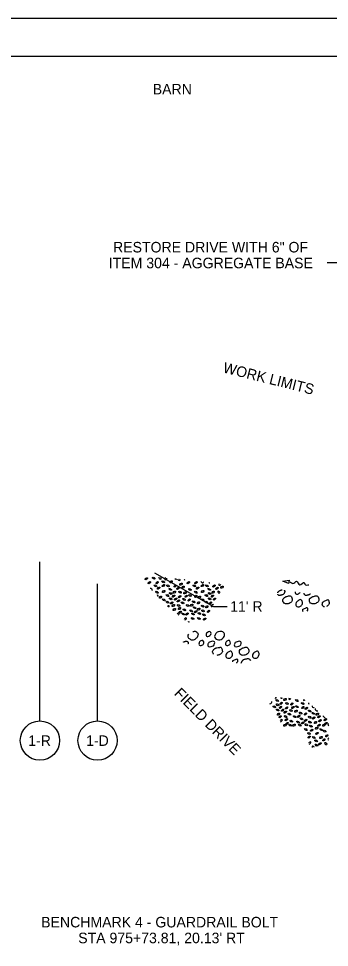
# Model space of a CAD drawing. Extents: x 1785 to 2465, y -264 to 295.
# Drawn here: x 2056 to 2138.7, y -70.6 to 176.2 of the extents above; entities that cross this region are included whole.
import ezdxf

# ---------------------------------------------------------------- set-up
doc = ezdxf.new("R2010")
doc.units = 0
for name, color, linetype in [('DR_P_Cells', 7, 'Continuous'), ('DR_P_Culvert', 7, 'Continuous'), ('DR_X_Erosion_Control', 7, 'Continuous'), ('PV_P_EOP', 7, 'Continuous'), ('PV_P_Shoulder', 7, 'Continuous'), ('RW_X_CL_100_Stations', 7, 'Continuous'), ('SV_X_Shot_Marker', 7, 'Continuous'), ('TX_P_1', 7, 'Continuous')]:
    doc.layers.add(name, color=color, linetype=linetype)

msp = doc.modelspace()

# ---------------------------------------------------------------- linework, layer by layer
at = {"layer": 'DR_P_Culvert'}
for p, q in [((2061.65, -10.42), (2061.65, 31.89)), ((2076.98, -10.42), (2076.98, 26.05))]:
    msp.add_line(p, q, dxfattribs=at)
at = {"layer": 'DR_X_Erosion_Control'}
for centre, major_axis in [((2089.96, 27.38), (0.296, 0.243)), ((2091.92, 27.55), (0.33, -0.195)), ((2090.77, 26.33), (0.296, 0.243)), ((2092.39, 25.49), (0.33, -0.195)), ((2092.84, 26.33), (0.296, 0.243)), ((2093.26, 24.89), (0.296, 0.243)), ((2094.45, 26.54), (0.33, -0.195)), ((2094.48, 25.56), (0.296, 0.243)), ((2095.72, 25.48), (0.33, -0.195)), ((2096.33, 24.56), (0.33, -0.195)), ((2096.57, 26.55), (0.296, 0.243)), ((2097.62, 25.45), (0.296, 0.243)), ((2098.38, 24.82), (0.296, 0.243)), ((2099.2, 25.92), (0.296, 0.243)), ((2099.74, 25.15), (0.296, 0.243)), ((2101.12, 26.33), (0.296, 0.243)), ((2101.55, 24.53), (0.33, -0.195)), ((2102.74, 25.49), (0.33, -0.195)), ((2103.19, 26.33), (0.296, 0.243)), ((2103.61, 24.89), (0.296, 0.243)), ((2104.83, 25.56), (0.296, 0.243)), ((2106.07, 25.48), (0.33, -0.195)), ((2106.68, 24.56), (0.33, -0.195)), ((2107.97, 25.45), (0.296, 0.243)), ((2108.73, 24.82), (0.296, 0.243)), ((2110.09, 25.15), (0.296, 0.243)), ((2092.77, 23.78), (0.33, -0.195)), ((2093.72, 22.49), (0.296, 0.243)), ((2094.59, 23.99), (0.296, 0.243)), ((2095.58, 22.89), (0.33, -0.195)), ((2096.44, 23.44), (0.33, -0.195)), ((2096.44, 22.04), (0.33, -0.195)), ((2097.21, 22.76), (0.296, 0.243)), ((2097.38, 23.8), (0.296, 0.243)), ((2097.74, 21.97), (0.296, 0.243)), ((2098.81, 22.6), (0.296, 0.243)), ((2098.93, 23.78), (0.33, -0.195)), ((2100.22, 23.64), (0.296, 0.243)), ((2100.54, 22.72), (0.296, 0.243)), ((2101.58, 22.92), (0.33, -0.195)), ((2103.12, 23.78), (0.33, -0.195)), ((2103.13, 22.69), (0.296, 0.243)), ((2104.07, 22.49), (0.296, 0.243)), ((2104.94, 23.99), (0.296, 0.243)), ((2105.93, 22.89), (0.33, -0.195)), ((2106.79, 23.44), (0.33, -0.195)), ((2106.79, 22.04), (0.33, -0.195)), ((2107.56, 22.76), (0.296, 0.243)), ((2107.73, 23.8), (0.296, 0.243)), ((2108.09, 21.97), (0.296, 0.243)), ((2094.61, 21.78), (0.33, -0.195)), ((2095.58, 21.16), (0.33, -0.195)), ((2096.68, 20.94), (0.296, 0.243)), ((2097.12, 20.26), (0.296, 0.243)), ((2098.47, 21.48), (0.296, 0.243)), ((2098.56, 20.28), (0.33, -0.195)), ((2098.78, 19.48), (0.296, 0.243)), ((2099.59, 20.96), (0.33, -0.195)), ((2100, 21.89), (0.33, -0.195)), ((2100.96, 20.27), (0.33, -0.195)), ((2101.34, 21.72), (0.296, 0.243)), ((2102.04, 20.36), (0.296, 0.243)), ((2102.57, 21.22), (0.33, -0.195)), ((2102.8, 19.68), (0.33, -0.195)), ((2103.84, 20.97), (0.296, 0.243)), ((2104.96, 21.78), (0.33, -0.195)), ((2104.96, 20.11), (0.33, -0.195)), ((2105.93, 21.16), (0.33, -0.195)), ((2106.04, 19.92), (0.296, 0.243)), ((2107.03, 20.94), (0.296, 0.243)), ((2097.39, 19.21), (0.296, 0.243)), ((2098.97, 18.49), (0.296, 0.243)), ((2099.78, 18), (0.33, -0.195)), ((2100.08, 19.09), (0.33, -0.195)), ((2100.8, 18), (0.296, 0.243)), ((2101.89, 18.84), (0.33, -0.195)), ((2102.36, 18), (0.33, -0.195)), ((2103.08, 18.61), (0.296, 0.243)), ((2103.88, 19.3), (0.296, 0.243)), ((2104.08, 18.12), (0.33, -0.195)), ((2105.04, 18.84), (0.33, -0.195)), ((2105.28, 17.77), (0.33, -0.195)), ((2106.5, 18.71), (0.296, 0.243)), ((2102.27, 16.83), (0.33, -0.195)), ((2103.94, 16.83), (0.33, -0.195)), ((2105.48, 16.66), (0.296, 0.243)), ((2124.77, -4.99), (0.33, -0.195)), ((2126.82, -4.73), (0.296, 0.243)), ((2130, -5.01), (0.33, -0.195)), ((2124.02, -6.65), (0.33, -0.195)), ((2124.89, -6.1), (0.33, -0.195)), ((2124.89, -7.51), (0.33, -0.195)), ((2125.65, -6.79), (0.296, 0.243)), ((2125.83, -5.74), (0.296, 0.243)), ((2126.18, -7.57), (0.296, 0.243)), ((2127.26, -6.95), (0.296, 0.243)), ((2127.37, -5.76), (0.33, -0.195)), ((2128.44, -7.65), (0.33, -0.195)), ((2128.66, -5.91), (0.296, 0.243)), ((2128.99, -6.82), (0.296, 0.243)), ((2130.03, -6.62), (0.33, -0.195)), ((2131.57, -5.77), (0.33, -0.195)), ((2131.58, -6.86), (0.296, 0.243)), ((2132.52, -7.06), (0.296, 0.243)), ((2125.12, -8.61), (0.296, 0.243)), ((2125.56, -9.29), (0.296, 0.243)), ((2126.92, -8.06), (0.296, 0.243)), ((2127, -9.26), (0.33, -0.195)), ((2127.22, -10.07), (0.296, 0.243)), ((2128.03, -8.59), (0.33, -0.195)), ((2129.41, -9.27), (0.33, -0.195)), ((2129.79, -7.82), (0.296, 0.243)), ((2130.48, -9.18), (0.296, 0.243)), ((2131.01, -8.32), (0.33, -0.195)), ((2131.24, -9.86), (0.33, -0.195)), ((2132.29, -8.57), (0.296, 0.243)), ((2133.41, -7.77), (0.33, -0.195)), ((2133.41, -9.44), (0.33, -0.195)), ((2134.37, -8.39), (0.33, -0.195)), ((2134.49, -9.62), (0.296, 0.243)), ((2135.47, -8.61), (0.296, 0.243)), ((2135.91, -9.29), (0.296, 0.243)), ((2137.57, -10.07), (0.296, 0.243)), ((2126.82, -11.55), (0.296, 0.243)), ((2127.42, -11.06), (0.296, 0.243)), ((2128.23, -11.54), (0.33, -0.195)), ((2128.52, -10.45), (0.33, -0.195)), ((2129.25, -11.54), (0.296, 0.243)), ((2130.34, -10.71), (0.33, -0.195)), ((2130.8, -11.54), (0.33, -0.195)), ((2131.53, -10.94), (0.296, 0.243)), ((2132.33, -10.25), (0.296, 0.243)), ((2132.53, -11.42), (0.33, -0.195)), ((2133.48, -10.71), (0.33, -0.195)), ((2133.73, -11.78), (0.33, -0.195)), ((2134.95, -10.84), (0.296, 0.243)), ((2135.28, -12.32), (0.296, 0.243)), ((2135.92, -11.56), (0.296, 0.243)), ((2136.18, -10.33), (0.296, 0.243)), ((2137.17, -11.55), (0.296, 0.243)), ((2137.76, -11.06), (0.296, 0.243)), ((2132.39, -12.72), (0.33, -0.195)), ((2133.24, -13.73), (0.33, -0.195)), ((2133.28, -14.7), (0.296, 0.243)), ((2133.93, -12.89), (0.296, 0.243)), ((2134.52, -14.79), (0.33, -0.195)), ((2135.36, -13.72), (0.296, 0.243)), ((2136.41, -14.82), (0.296, 0.243)), ((2136.48, -12.73), (0.33, -0.195)), ((2137.4, -13.11), (0.33, -0.195)), ((2137.99, -14.35), (0.296, 0.243)), ((2135.12, -15.71), (0.33, -0.195)), ((2135.24, -16.82), (0.33, -0.195)), ((2136.18, -16.47), (0.296, 0.243)), ((2137.17, -15.45), (0.296, 0.243))]:
    msp.add_ellipse(centre, major_axis=major_axis, ratio=0.503326, dxfattribs=at)
for centre, major_axis, start_param, end_param in [((2093.59, 27.55), (0.33, -0.195), 3.081648, 6.283185), ((2093.59, 27.55), (0.33, -0.195), 0, 1.583283), ((2095.13, 27.38), (0.296, 0.243), 1.262331, 5.971541), ((2097.69, 27.54), (0.33, -0.195), 4.661673, 6.283185), ((2097.69, 27.54), (0.33, -0.195), 0, 0.003258), ((2098.61, 27.16), (0.33, -0.195), 3.317728, 6.283185), ((2098.61, 27.16), (0.33, -0.195), 0, 1.347202), ((2100.31, 27.38), (0.296, 0.243), 2.934728, 4.235957), ((2091.2, 24.53), (0.33, -0.195), 0, 2.55882), ((2104.8, 26.54), (0.33, -0.195), 3.736707, 6.283185), ((2104.8, 26.54), (0.33, -0.195), 0, 0.823435), ((2106.92, 26.55), (0.296, 0.243), 2.964771, 4.205915), ((2109.55, 25.92), (0.296, 0.243), 1.874215, 5.29647), ((2091.2, 24.53), (0.33, -0.195), 5.834784, 6.283185), ((2092.78, 22.69), (0.296, 0.243), 0, 1.242704), ((2092.78, 22.69), (0.296, 0.243), 5.112248, 6.283185), ((2109.28, 23.78), (0.33, -0.195), 0.760733, 5.482792), ((2095.69, 19.92), (0.296, 0.243), 0, 1.771206), ((2095.69, 19.92), (0.296, 0.243), 4.746136, 6.283185), ((2107.47, 20.26), (0.296, 0.243), 0, 4.95729), ((2107.47, 20.26), (0.296, 0.243), 5.940076, 6.283185), ((2098.38, 18), (0.296, 0.243), 0, 2.058987), ((2098.38, 18), (0.296, 0.243), 4.458354, 6.283185), ((2100.31, 16.66), (0.296, 0.243), 0, 2.389821), ((2100.31, 16.66), (0.296, 0.243), 4.127521, 6.283185), ((2101.12, 15.61), (0.296, 0.243), 0, 1.432331), ((2101.12, 15.61), (0.296, 0.243), 6.04233, 6.283185), ((2124.17, -4.07), (0.33, -0.195), 5.014572, 6.283185), ((2124.17, -4.07), (0.33, -0.195), 0, 0.813102), ((2126.06, -4.1), (0.296, 0.243), 2.496073, 4.729225), ((2128.18, -4.4), (0.296, 0.243), 2.124737, 5.100561), ((2132.06, -4.66), (0.296, 0.243), 2.449695, 4.775603), ((2123.04, -5.55), (0.296, 0.243), 3.698029, 6.283185), ((2123.04, -5.55), (0.296, 0.243), 0, 0.128607), ((2133.39, -5.55), (0.296, 0.243), 2.151782, 4.285805), ((2134.37, -6.65), (0.33, -0.195), 2.866345, 5.804923), ((2135.24, -7.51), (0.33, -0.195), 2.57753, 6.093738), ((2137.35, -9.26), (0.33, -0.195), 3.0967, 5.574568), ((2125.83, -10.33), (0.296, 0.243), 0, 2.3621), ((2125.83, -10.33), (0.296, 0.243), 3.766158, 6.283185), ((2138.58, -11.54), (0.33, -0.195), 2.00268, 4.858682), ((2133.39, -16.28), (0.296, 0.243), 0, 2.067896), ((2133.39, -16.28), (0.296, 0.243), 3.928937, 6.283185), ((2134.37, -17.38), (0.33, -0.195), 0.77197, 4.49771), ((2137.72, -16.49), (0.33, -0.195), 0, 5.472138), ((2137.72, -16.49), (0.33, -0.195), 6.080726, 6.283185), ((2138.53, -15.12), (0.296, 0.243), 1.180667, 4.317924)]:
    msp.add_ellipse(centre, major_axis=major_axis, ratio=0.503326, start_param=start_param, end_param=end_param, dxfattribs=at)
at = {"layer": 'PV_P_EOP'}
for p, q in [((2126.3, 26.77), (2127.94, 26.97)), ((2127.82, 26.12), (2126.3, 26.77)), ((2127.94, 26.97), (2127.82, 26.12))]:
    msp.add_line(p, q, dxfattribs=at)
msp.add_spline([(2127.88, 26.54), (2127.94, 26.53), (2128.58, 26.29), (2128.97, 26.09), (2129.91, 26.7), (2130.76, 25.74), (2131.98, 26.41), (2132.14, 25.93), (2133.23, 25.79)], degree=3, dxfattribs=at)
at = {"layer": 'PV_P_Shoulder'}
for points in [[(2126.61, 24.33), (2126.64, 24.31), (2126.66, 24.29), (2126.69, 24.26), (2126.81, 24.14), (2126.8, 23.98), (2126.76, 23.85), (2126.7, 23.64), (2126.62, 23.43), (2126.42, 23.26), (2126.22, 23.09), (2126.01, 23.07), (2125.79, 23.02), (2125.57, 22.97), (2125.31, 22.83), (2125.09, 23.03), (2125, 23.11), (2124.96, 23.19), (2124.94, 23.28)], [(2124.94, 23.66), (2124.95, 23.73), (2124.98, 23.8), (2125.02, 23.86), (2125.07, 23.93), (2125.12, 23.99), (2125.17, 24.06)], [(2125.17, 24.06), (2125.34, 24.14), (2125.5, 24.22), (2125.67, 24.31), (2125.79, 24.37), (2125.92, 24.39), (2126.06, 24.41)], [(2130.83, 23.73), (2130.73, 23.59), (2130.59, 23.46), (2130.46, 23.36), (2130.25, 23.2), (2129.81, 23.22), (2129.68, 23.47), (2129.62, 23.6), (2129.64, 23.76), (2129.67, 23.9)], [(2133.58, 23.34), (2133.55, 23.32), (2133.52, 23.29), (2133.49, 23.26), (2133.29, 23.09), (2133.08, 23.07), (2132.86, 23.02), (2132.64, 22.97), (2132.38, 22.83), (2132.16, 23.03), (2132.01, 23.16), (2131.98, 23.31), (2131.99, 23.46), (2131.99, 23.5), (2131.99, 23.53), (2131.99, 23.57)], [(2131.66, 19.32), (2131.97, 19.45), (2132.29, 19.59), (2132.61, 19.71), (2132.76, 19.77), (2132.84, 19.42), (2132.86, 19.27), (2132.87, 19.11), (2132.78, 18.95), (2132.66, 18.8)], [(2137.4, 19.87), (2137.28, 19.87), (2137.16, 19.92), (2137.05, 20.02), (2136.82, 20.25), (2136.74, 20.51), (2136.79, 20.74), (2136.82, 20.92), (2136.91, 21.16), (2137.08, 21.27), (2137.2, 21.36), (2137.32, 21.43), (2137.45, 21.51)], [(2137.45, 21.51), (2137.68, 21.61), (2137.91, 21.71), (2138.15, 21.81), (2138.39, 21.92), (2138.51, 21.39), (2138.56, 21.14), (2138.62, 20.88), (2138.55, 20.58), (2138.34, 20.33), (2138.2, 20.15), (2138.04, 20.05), (2137.87, 19.97)], [(2131.64, 18.56), (2131.6, 18.7), (2131.59, 18.84), (2131.58, 18.98), (2131.58, 19.06), (2131.55, 19.15), (2131.59, 19.22), (2131.61, 19.26), (2131.64, 19.29), (2131.66, 19.32)], [(2102.29, 13.32), (2102.33, 13.33), (2102.36, 13.34), (2102.4, 13.35), (2102.74, 13.44), (2103.09, 13.38), (2103.44, 13.09), (2103.71, 12.86), (2103.73, 12.53), (2103.65, 12.28), (2103.56, 11.97), (2103.37, 11.67), (2103.06, 11.41), (2102.68, 11.09), (2102.16, 10.96), (2101.77, 11.19), (2101.45, 11.38), (2101.12, 11.66), (2101.06, 11.99), (2101.02, 12.19), (2101.13, 12.43), (2101.24, 12.62)], [(2099.81, 10.55), (2099.86, 10.58), (2099.92, 10.61), (2099.97, 10.64), (2100.15, 10.73), (2100.37, 10.75), (2100.57, 10.75), (2100.72, 10.76), (2100.86, 10.72), (2100.99, 10.59), (2101.12, 10.47), (2101.1, 10.31), (2101.06, 10.18), (2101.05, 10.14), (2101.04, 10.11), (2101.03, 10.07)], [(2107.83, 7.36), (2107.82, 7.39), (2107.8, 7.42), (2107.78, 7.44), (2107.61, 7.71), (2107.56, 8.08), (2107.71, 8.33), (2107.81, 8.5), (2107.94, 8.65), (2108.12, 8.76), (2108.26, 8.85), (2108.4, 8.94), (2108.57, 8.98), (2108.62, 8.99), (2108.68, 9), (2108.73, 9.01)], [(2108.72, 9.01), (2109.02, 9.06), (2109.32, 9.12), (2109.62, 9.16), (2109.93, 9.2), (2110.07, 8.68), (2110.14, 8.4), (2110.21, 8.14), (2110.17, 7.83), (2109.95, 7.59), (2109.68, 7.29), (2109.39, 7.18), (2109.06, 7.08), (2108.95, 7.05), (2108.83, 7.02), (2108.72, 7.01)], [(2112.95, 5.33), (2112.95, 5.4), (2112.93, 5.48), (2112.96, 5.55), (2112.99, 5.59), (2113.01, 5.62), (2113.03, 5.65)], [(2113.03, 5.65), (2113.35, 5.78), (2113.66, 5.92), (2113.98, 6.04), (2114.14, 6.1), (2114.22, 5.75), (2114.23, 5.6), (2114.25, 5.4), (2114.1, 5.19), (2113.93, 5), (2113.92, 4.98), (2113.91, 4.97), (2113.9, 4.95)], [(2115.21, 4.95), (2115.24, 5.09), (2115.31, 5.24), (2115.39, 5.36), (2115.48, 5.5), (2115.55, 5.64), (2115.67, 5.75), (2115.72, 5.8), (2115.78, 5.85), (2115.83, 5.9)], [(2115.83, 5.9), (2116.07, 5.97), (2116.3, 6.03), (2116.54, 6.09), (2116.89, 6.18), (2117.24, 6.12), (2117.58, 5.83), (2117.65, 5.77), (2117.7, 5.71), (2117.74, 5.64)]]:
    msp.add_open_spline(points, degree=3, dxfattribs=at)
for points in [[(2127.34, 22.68), (2128.25, 22.83), (2128.77, 22.07), (2128.58, 21.26), (2127.68, 20.75), (2126.8, 20.76), (2126.41, 21.11), (2126.33, 22), (2126.74, 22.43), (2127.19, 22.65), (2127.36, 22.68)], [(2134.41, 22.68), (2135.32, 22.83), (2135.84, 22.07), (2135.65, 21.26), (2134.76, 20.75), (2133.88, 20.76), (2133.48, 21.11), (2133.4, 22), (2133.81, 22.43), (2134.27, 22.65), (2134.43, 22.68)], [(2130.37, 21.51), (2131.08, 21.81), (2131.49, 21.14), (2131.27, 20.33), (2130.6, 19.9), (2129.98, 20.02), (2129.71, 20.74), (2130.01, 21.27), (2130.37, 21.51)], [(2105.96, 12.91), (2106.91, 13.3), (2107.16, 12.86), (2106.86, 12.26), (2105.96, 12.09), (2105.88, 12.57), (2105.89, 12.81), (2105.96, 12.91)], [(2108.76, 13.17), (2109.47, 13.35), (2110.51, 13.09), (2110.73, 12.28), (2110.13, 11.41), (2108.84, 11.19), (2108.13, 11.99), (2108.32, 12.63), (2108.6, 13.01), (2108.76, 13.17)], [(2104.27, 10.82), (2105.03, 10.93), (2105.24, 10.27), (2104.76, 9.69), (2103.99, 9.8), (2103.99, 10.29), (2104.11, 10.62), (2104.27, 10.82)], [(2106.54, 10.39), (2107.04, 10.64), (2107.64, 10.75), (2108.07, 10.59), (2108.13, 10.18), (2107.79, 9.59), (2107.17, 9.35), (2106.46, 9.36), (2106.29, 9.79), (2106.39, 10.19), (2106.54, 10.39)], [(2111.34, 10.82), (2112.1, 10.93), (2112.31, 10.27), (2111.83, 9.69), (2111.06, 9.8), (2111.06, 10.29), (2111.18, 10.62), (2111.34, 10.82)], [(2113.61, 10.39), (2114.11, 10.64), (2114.72, 10.75), (2115.14, 10.59), (2115.21, 10.18), (2114.86, 9.59), (2114.24, 9.35), (2113.53, 9.36), (2113.36, 9.79), (2113.47, 10.19), (2113.61, 10.39)], [(2111.75, 7.84), (2112.45, 8.14), (2112.87, 7.47), (2112.64, 6.66), (2111.98, 6.23), (2111.35, 6.35), (2111.09, 7.07), (2111.38, 7.6), (2111.75, 7.84)], [(2115.79, 9.01), (2116.7, 9.16), (2117.21, 8.4), (2117.02, 7.59), (2116.13, 7.08), (2115.25, 7.09), (2114.85, 7.44), (2114.78, 8.33), (2115.19, 8.76), (2115.64, 8.98), (2115.8, 9.01)], [(2118.82, 7.84), (2119.52, 8.14), (2119.94, 7.47), (2119.71, 6.66), (2119.05, 6.23), (2118.43, 6.35), (2118.16, 7.07), (2118.45, 7.6), (2118.82, 7.84)]]:
    msp.add_spline(points, degree=3, dxfattribs=at)
at = {"layer": 'RW_X_CL_100_Stations'}
msp.add_lwpolyline([(1814.87, 166.23), (2454.87, 166.23), (2454.87, -253.77), (1814.87, -253.77)], close=True, dxfattribs=at)
at = {"layer": 'SV_X_Shot_Marker'}
msp.add_lwpolyline([(1784.87, -263.77), (2464.87, -263.77), (2464.87, 176.23), (1784.87, 176.23)], close=True, dxfattribs=at)
at = {"layer": 'TX_P_1'}
for p, q in [((2142.67, 111.28), (2138.06, 111.28)), ((2092.09, 28.98), (2107.82, 20.01)), ((2107.82, 20.01), (2111.43, 20.01))]:
    msp.add_line(p, q, dxfattribs=at)
for centre in [(2061.65, -15.64), (2076.98, -15.64)]:
    msp.add_circle(centre, 5.22, dxfattribs=at)

# ---------------------------------------------------------------- texts
at = {"layer": 'DR_P_Cells'}
for s, p in [('BENCHMARK 4 - GUARDRAIL BOLT', (2061.98, -65.28)), ("STA 975+73.81, 20.13' RT", (2071.83, -69.48))]:
    msp.add_text(s, height=2.8, dxfattribs=at).set_placement(p)
at = {"layer": 'DR_P_Culvert'}
msp.add_text('BARN', height=2.8, dxfattribs=at).set_placement((2091.66, 156.07))
msp.add_text('FIELD DRIVE', height=2.8, rotation=314.5898, dxfattribs=at).set_placement((2097.17, -3.28))
at = {"layer": 'TX_P_1'}
for s, p in [('RESTORE DRIVE WITH 6" OF', (2081.1, 114.08)), ('ITEM 304 - AGGREGATE BASE', (2079.96, 109.88)), ("11' R", (2112.26, 18.61)), ('1-R', (2058.53, -17.04)), ('1-D', (2073.93, -17.04))]:
    msp.add_text(s, height=2.8, dxfattribs=at).set_placement(p)
msp.add_text('WORK LIMITS', height=2.8, rotation=346.0179, dxfattribs=at).set_placement((2110.15, 82.23))

doc.saveas('drawing.dxf')
